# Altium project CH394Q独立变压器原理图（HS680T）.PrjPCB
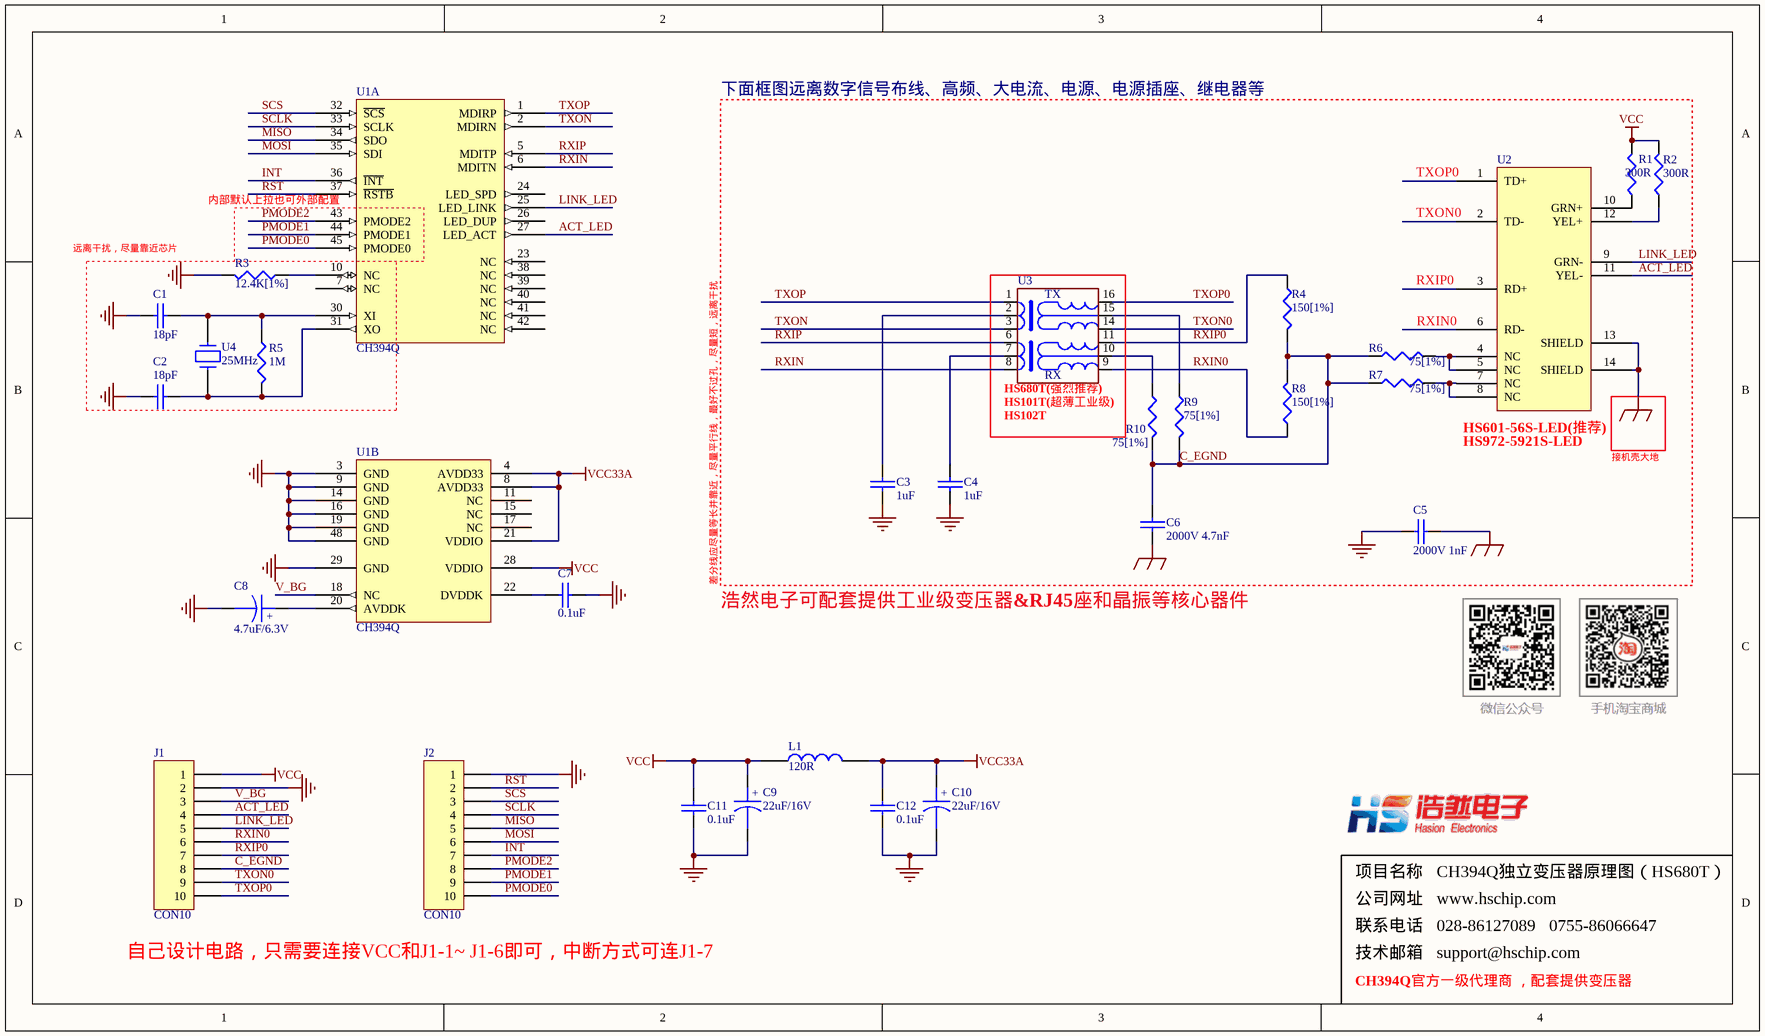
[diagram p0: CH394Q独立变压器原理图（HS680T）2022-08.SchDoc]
1 sheet, 29 parts. Net scope: global (net labels, ports and power ports of the same name join across sheets).

## Sheet CH394Q独立变压器原理图（HS680T）2022-08.SchDoc
size 330 x 193 mm; SheetNumber: 0; SheetTotal: 0; PageSetup: Record=PageOptions?CenterHorizontal=True?CenterVertical=True?PrintScale=0.89?XCorrection=1.00?YCorrection=1.00?PrintKind=0?BorderSize=5000000?LeftOffset=0?BottomOffset=0?Orientation=2?PaperLength=1000?PaperWidth=1000?Scale=100?PaperSource=7?PrintQuality=-4?MediaType=1?DitherType=10?PaperKind=A4?PrintScaleMode=1

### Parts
C1  18pF  [0603]
C2  18pF  [0603]
C3  1uF  [0603]
C4  1uF  [0603]
C5  2000V 1nF  [0603]
C6  2000V 4.7nF  [0603]
C7  0.1uF  [0603]
C8  4.7uF/6.3V  [3216]
C9  22uF/16V  [3216]
C10  22uF/16V  [3216]
C11  0.1uF  [0603]
C12  0.1uF  [0603]
J1  CON10  [SIP10]
J2  CON10  [SIP10]
L1  120R  [0603]
R1  300R  [0603]
R2  300R  [0603]
R3  12.4K[1%]  [0603]
R4  150[1%]  [0603]
R5  1M  [0603]
R6  75[1%]  [0603]
R7  75[1%]  [0603]
R8  150[1%]  [0603]
R9  75[1%]  [0603]
R10  75[1%]  [0603]
U1  CH394Q  [LQFP48]  (parts A,B of 2)
U2  HS601-56S-LED(推荐)  [RJ45-HS601-56S-LED]
U3  HS102T  [TR-HS101T/HS102T/HS680T]
U4  25MHz  [XTAL-49S]

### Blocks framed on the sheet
下面框图远离数字信号布线、高频、大电流、电源、电源插座、继电器等: C3-C6 R1 R2 R4 R6-R10 U2 U3

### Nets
EARTH: C5.1 C6.1 U2.13(SHIELD) U2.14(SHIELD)
GND: C1.2 C2.2 C3.1 C4.1 C5.2 C7.1 C8.2 C9.2 C10.2 C11.2 C12.2 J1.2 J2.1 R3.2 U1.3(GND) U1.9(GND) U1.14(GND) U1.16(GND) U1.19(GND) U1.29(GND) U1.48(GND)
VCC: C9.1 C11.1 J1.1 L1.1 R1.2 R2.2 U1.28(VDDIO)
VCC33A: C10.1 C12.1 L1.2 U1.4(AVDD33) U1.8(AVDD33) U1.21(VDDIO)
ACT_LED: J1.4 U1.27(LED_ACT) U2.11(YEL-)
C_EGND: C6.2 J1.8 R4.2 R6.1 R7.1 R8.2 R9.2 R10.2
INT: J2.7 U1.36(~{INT})
LINK_LED: J1.5 U1.25(LED_LINK) U2.9(GRN-)
MISO: J2.5 U1.34(SDO)
MOSI: J2.6 U1.35(SDI)
PMODE0: J2.10 U1.45(PMODE0)
PMODE1: J2.9 U1.44(PMODE1)
PMODE2: J2.8 U1.43(PMODE2)
RST: J2.2 U1.37(~{RSTB})
RXIN: U1.6(MDITN) U3.8
RXIN0: J1.6 R8.1 U3.9
RXIP: U1.5(MDITP) U3.6
RXIP0: J1.7 R4.1 U2.3(RD+) U3.11
SCLK: J2.4 U1.33(SCLK)
SCS: J2.3 U1.32(~{SCS})
TXON: U1.2(MDIRN) U3.3
TXON0: J1.9 U2.2(TD-) U3.14
TXOP: U1.1(MDIRP) U3.1
TXOP0: J1.10 U2.1(TD+) U3.16
V_BG: J1.3 U1.18(NC)
NetC1_1: C1.1 R5.1 U1.30(XI) U4.1
NetC2_1: C2.1 R5.2 U1.31(XO) U4.2
NetC3_2: C3.2 U3.2
NetC4_2: C4.2 U3.7
NetC7_2: C7.2 U1.22(DVDDK)
NetC8_1: C8.1 U1.20(AVDDK)
NetR1_1: R1.1 U2.10(GRN+)
NetR2_1: R2.1 U2.12(YEL+)
NetR3_1: R3.1 U1.10(NC)
NetR6_2: R6.2 U2.4(NC) U2.5(NC)
NetR7_2: R7.2 U2.7(NC) U2.8(NC)
NetR9_1: R9.1 U3.15
NetR10_1: R10.1 U3.10

Not connected (* = marked no-connect by the designer): U1 7(NC) 11(NC) 15(NC) 17(NC) 23(NC) 24(LED_SPD) 26(LED_DUP) 38(NC) 39(NC) 40(NC) 41(NC) 42(NC); U2 6(RD-)

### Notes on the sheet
- 远离干扰，尽量靠近芯片
- 内部默认上拉也可外部配置
- (near U3) HS101T(超薄工业级)
- (near U3) HS680T(强烈推荐)
- (near U2) HS972-5921S-LED
- 接机壳大地
- 差分线应尽量等长并靠近，尽量平行线，最好不过孔，尽量短，远离干扰
- 公司网址   www.hschip.com
- 项目名称   CH394Q独立变压器原理图（HS680T）
- 自己设计电路，只需要连接VCC和J1-1~ J1-6即可，中断方式可连J1-7
- 联系电话   028-86127089   0755-86066647
- CH394Q官方一级代理商 ，配套提供变压器
- 技术邮箱   support@hschip.com
- Labels drawn without touching a wire or pin: RXIN0, 浩然电子可配套提供工业级变压器&RJ45座和晶振等核心器件

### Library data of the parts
C1-C7 C11 C12 = CAP: Capacitor
C8-C10 = CAPACITOR POL: Capacitor
J1 J2 = CON10: Connector
L1 = INDUCTOR
R1-R10 = RES1
U2 = HS601 /HS972
U4 = CRYSTAL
